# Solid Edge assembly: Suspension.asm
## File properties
Author: wojci
Template: iso metric assembly.asm
Last saved by: wojci
Revision: 23
Application: Solid Edge
Username: wojci
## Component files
Lever.par
SupportBack.par
Servo.par
RotaryTrackerLeft.par
MountingPlate.par
Hold.par
RotaryTrackerRight.par
SupportFront.par
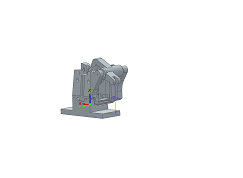
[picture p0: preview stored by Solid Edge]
